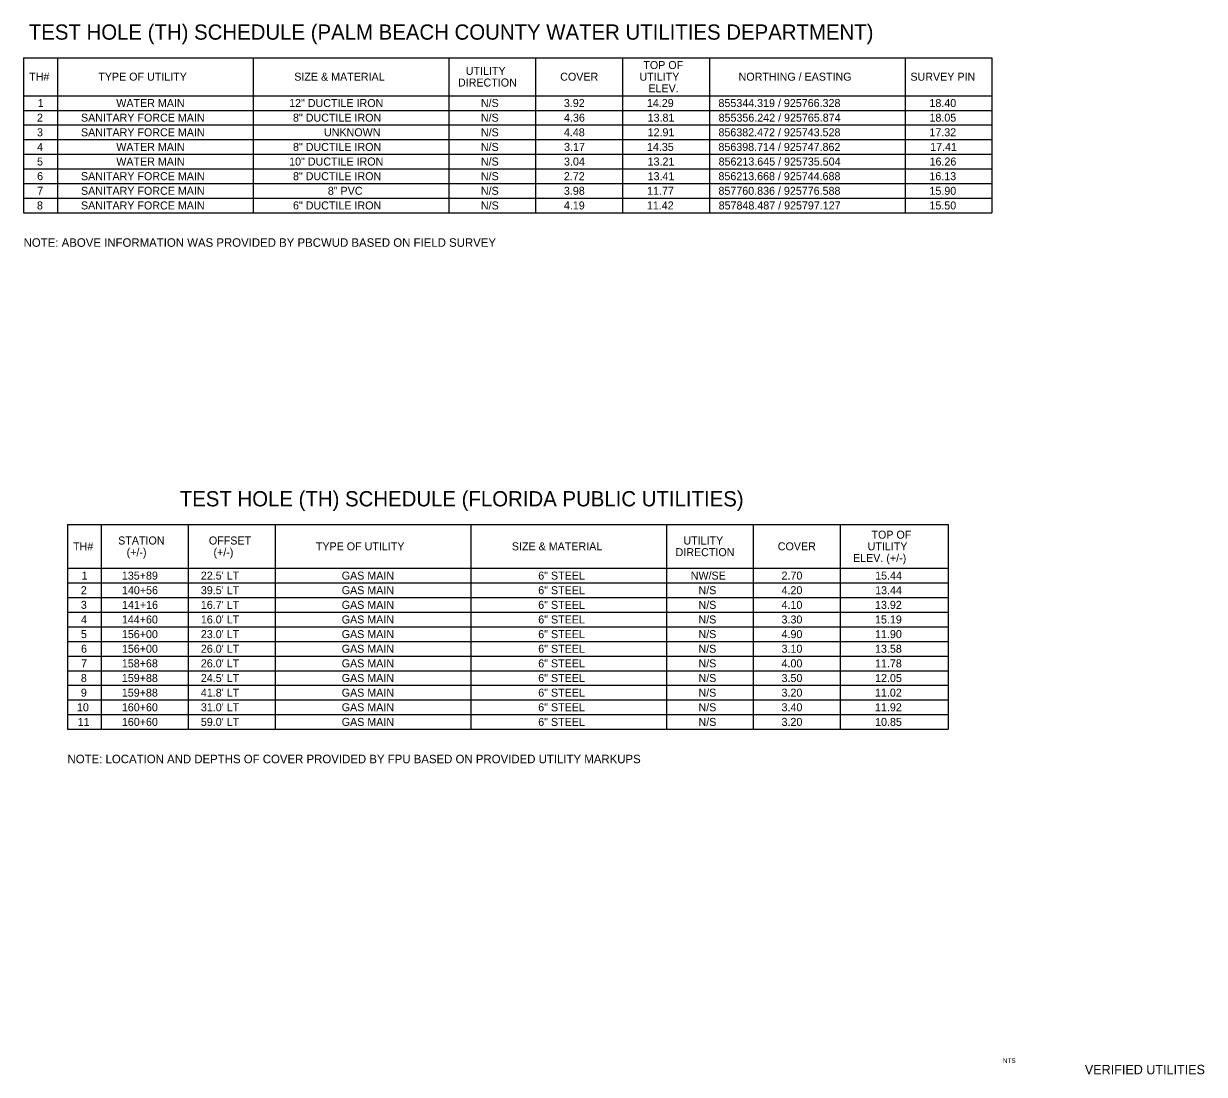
# Model space of a CAD drawing. Extents: x 3.74 to 13.42, y -0.23 to 8.39.
import ezdxf

# ---------------------------------------------------------------- set-up
doc = ezdxf.new("R2010")
doc.units = 0
for name, color, linetype in [('Default', 7, 'Continuous'), ('SumBoxBorder_dp', 7, 'Continuous'), ('SumBoxLines_dp', 7, 'Continuous'), ('TextLabel', 7, 'Continuous'), ('TextMinor', 7, 'Continuous')]:
    doc.layers.add(name, color=color, linetype=linetype)

msp = doc.modelspace()

# ---------------------------------------------------------------- linework, layer by layer
at = {"layer": 'SumBoxBorder_dp'}
for p, q in [((3.7378, 8.1135), (11.6803, 8.1135)), ((3.7378, 8.1135), (3.7378, 6.8415)), ((11.6803, 8.1135), (11.6803, 6.8415)), ((3.7378, 7.8015), (11.6803, 7.8015)), ((3.7378, 7.8015), (11.6803, 7.8015)), ((4.0978, 4.2857), (11.3203, 4.2857)), ((4.0978, 4.2857), (4.0978, 2.6057)), ((4.0978, 3.9257), (11.3203, 3.9257)), ((4.0978, 3.9257), (11.3203, 3.9257))]:
    msp.add_line(p, q, dxfattribs=at)
at = {"layer": 'SumBoxLines_dp'}
for p, q in [((4.0153, 8.1135), (4.0153, 6.8415)), ((4.0153, 8.1135), (4.0153, 6.8415)), ((5.6203, 8.1135), (5.6203, 6.8415)), ((5.6203, 8.1135), (5.6203, 6.8415)), ((7.2253, 8.1135), (7.2253, 6.8415)), ((7.2253, 8.1135), (7.2253, 6.8415)), ((7.9378, 8.1135), (7.9378, 6.8415)), ((7.9378, 8.1135), (7.9378, 6.8415)), ((8.6503, 8.1135), (8.6503, 6.8415)), ((8.6503, 8.1135), (8.6503, 6.8415)), ((9.3628, 8.1135), (9.3628, 6.8415)), ((9.3628, 8.1135), (9.3628, 6.8415)), ((10.9678, 8.1135), (10.9678, 6.8415)), ((10.9678, 8.1135), (10.9678, 6.8415)), ((3.7378, 7.6815), (11.6803, 7.6815)), ((3.7378, 7.6815), (11.6803, 7.6815)), ((3.7378, 7.5615), (11.6803, 7.5615)), ((3.7378, 7.5615), (11.6803, 7.5615)), ((3.7378, 7.4415), (11.6803, 7.4415)), ((3.7378, 7.4415), (11.6803, 7.4415)), ((3.7378, 7.3215), (11.6803, 7.3215)), ((3.7378, 7.3215), (11.6803, 7.3215)), ((3.7378, 7.2015), (11.6803, 7.2015)), ((3.7378, 7.2015), (11.6803, 7.2015)), ((3.7378, 7.0815), (11.6803, 7.0815)), ((3.7378, 7.0815), (11.6803, 7.0815)), ((3.7378, 6.9615), (11.6803, 6.9615)), ((3.7378, 6.9615), (11.6803, 6.9615)), ((3.7378, 6.8415), (11.6803, 6.8415)), ((4.3753, 4.2857), (4.3753, 2.6057)), ((4.3753, 4.2857), (4.3753, 2.6057)), ((5.0878, 4.2857), (5.0878, 2.6057)), ((5.0878, 4.2857), (5.0878, 2.6057)), ((5.8003, 4.2857), (5.8003, 2.6057)), ((5.8003, 4.2857), (5.8003, 2.6057)), ((7.4053, 4.2857), (7.4053, 2.6057)), ((7.4053, 4.2857), (7.4053, 2.6057)), ((9.0103, 4.2857), (9.0103, 2.6057)), ((9.0103, 4.2857), (9.0103, 2.6057)), ((9.7228, 4.2857), (9.7228, 2.6057)), ((9.7228, 4.2857), (9.7228, 2.6057)), ((10.4353, 4.2857), (10.4353, 2.6057)), ((10.4353, 4.2857), (10.4353, 2.6057)), ((11.3203, 4.2857), (11.3203, 2.6057)), ((4.0978, 3.8057), (11.3203, 3.8057)), ((4.0978, 3.8057), (11.3203, 3.8057)), ((4.0978, 3.6857), (11.3203, 3.6857)), ((4.0978, 3.6857), (11.3203, 3.6857)), ((4.0978, 3.5657), (11.3203, 3.5657)), ((4.0978, 3.5657), (11.3203, 3.5657)), ((4.0978, 3.4457), (11.3203, 3.4457)), ((4.0978, 3.4457), (11.3203, 3.4457)), ((4.0978, 3.3257), (11.3203, 3.3257)), ((4.0978, 3.3257), (11.3203, 3.3257)), ((4.0978, 3.2057), (11.3203, 3.2057)), ((4.0978, 3.2057), (11.3203, 3.2057)), ((4.0978, 3.0857), (11.3203, 3.0857)), ((4.0978, 3.0857), (11.3203, 3.0857)), ((4.0978, 2.9657), (11.3203, 2.9657)), ((4.0978, 2.9657), (11.3203, 2.9657)), ((4.0978, 2.8457), (11.3203, 2.8457)), ((4.0978, 2.8457), (11.3203, 2.8457)), ((4.0978, 2.7257), (11.3203, 2.7257)), ((4.0978, 2.7257), (11.3203, 2.7257)), ((4.0978, 2.6057), (11.3203, 2.6057))]:
    msp.add_line(p, q, dxfattribs=at)

# ---------------------------------------------------------------- texts
at = {"layer": 'Default'}
msp.add_text('   VERIFIED UTILITIES   ', height=0.077091, dxfattribs=at).set_placement((12.3568, -0.2241))
at = {"layer": 'TextLabel'}
for s, height, p in [('TEST HOLE (TH) SCHEDULE (PALM BEACH COUNTY WATER UTILITIES DEPARTMENT)', 0.125, (3.7804, 8.2611)), ('TOP OF', 0.06563, (8.8213, 8.0203)), ('TH#', 0.06563, (3.7835, 7.9247)), ('TYPE OF UTILITY', 0.065625, (4.3502, 7.9247)), ('SIZE & MATERIAL', 0.065625, (5.958, 7.9247)), ('DIRECTION', 0.06563, (7.3008, 7.8769)), ('UTILITY', 0.06563, (7.3645, 7.9725)), ('COVER', 0.06563, (8.1391, 7.9247)), ('UTILITY', 0.06563, (8.7895, 7.9247)), ('NORTHING / EASTING', 0.065625, (9.6027, 7.9247)), ('SURVEY PIN', 0.06563, (11.012, 7.9247)), ('ELEV.', 0.06563, (8.8625, 7.829)), ('1', 0.0656, (3.8537, 7.7087)), ('WATER MAIN', 0.06563, (4.498, 7.7087)), ('12" DUCTILE IRON', 0.065625, (5.9159, 7.7087)), ('N/S', 0.06563, (7.4886, 7.7087)), ('3.92', 0.06563, (8.1694, 7.7087)), ('14.29', 0.06563, (8.8505, 7.7087)), ('855344.319 / 925766.328', 0.065625, (9.4374, 7.7087)), ('18.40', 0.06563, (11.1681, 7.7087)), ('2', 0.0656, (3.8473, 7.5887)), ('SANITARY FORCE MAIN', 0.065625, (4.2083, 7.5887)), ('8" DUCTILE IRON', 0.065625, (5.9476, 7.5887)), ('N/S', 0.06563, (7.4886, 7.5887)), ('4.36', 0.06563, (8.1707, 7.5887)), ('13.81', 0.06563, (8.8564, 7.5887)), ('855356.242 / 925765.874', 0.065625, (9.4385, 7.5887)), ('18.05', 0.06563, (11.1684, 7.5887)), ('3', 0.0656, (3.8472, 7.4687)), ('SANITARY FORCE MAIN', 0.065625, (4.2083, 7.4687)), ('UNKNOWN', 0.06563, (6.2017, 7.4687)), ('N/S', 0.06563, (7.4886, 7.4687)), ('4.48', 0.06563, (8.1696, 7.4687)), ('12.91', 0.06563, (8.8564, 7.4687)), ('856382.472 / 925743.528', 0.065625, (9.4374, 7.4687)), ('17.32', 0.06563, (11.1676, 7.4687)), ('4', 0.0656, (3.8486, 7.3487)), ('WATER MAIN', 0.06563, (4.498, 7.3487)), ('8" DUCTILE IRON', 0.065625, (5.9476, 7.3487)), ('N/S', 0.06563, (7.4886, 7.3487)), ('3.17', 0.06563, (8.1712, 7.3487)), ('14.35', 0.06563, (8.8509, 7.3487)), ('856398.714 / 925747.862', 0.065625, (9.4372, 7.3487)), ('17.41', 0.06563, (11.1739, 7.3487)), ('5', 0.0656, (3.8481, 7.2287)), ('WATER MAIN', 0.06563, (4.498, 7.2287)), ('10" DUCTILE IRON', 0.065625, (5.9159, 7.2287)), ('N/S', 0.06563, (7.4886, 7.2287)), ('3.04', 0.06563, (8.1706, 7.2287)), ('13.21', 0.06563, (8.8564, 7.2287)), ('856213.645 / 925735.504', 0.065625, (9.4385, 7.2287)), ('16.26', 0.06563, (11.1689, 7.2287)), ('6', 0.0656, (3.8485, 7.1087)), ('SANITARY FORCE MAIN', 0.065625, (4.2083, 7.1087)), ('8" DUCTILE IRON', 0.065625, (5.9476, 7.1087)), ('N/S', 0.06563, (7.4886, 7.1087)), ('2.72', 0.06563, (8.1694, 7.1087)), ('13.41', 0.06563, (8.8564, 7.1087)), ('856213.668 / 925744.688', 0.065625, (9.4374, 7.1087)), ('16.13', 0.06563, (11.1676, 7.1087)), ('7', 0.0656, (3.8493, 6.9887)), ('SANITARY FORCE MAIN', 0.065625, (4.2083, 6.9887)), ('8" PVC', 0.06563, (6.2333, 6.9887)), ('N/S', 0.06563, (7.4886, 6.9887)), ('3.98', 0.06563, (8.1696, 6.9887)), ('11.77', 0.06563, (8.852, 6.9887)), ('857760.836 / 925776.588', 0.065625, (9.4374, 6.9887)), ('15.90', 0.06563, (11.1681, 6.9887)), ('8', 0.0656, (3.8475, 6.8687)), ('SANITARY FORCE MAIN', 0.065625, (4.2083, 6.8687)), ('6" DUCTILE IRON', 0.065625, (5.9476, 6.8687)), ('N/S', 0.06563, (7.4886, 6.8687)), ('4.19', 0.06563, (8.1697, 6.8687)), ('11.42', 0.06563, (8.8501, 6.8687)), ('857848.487 / 925797.127', 0.065625, (9.439, 6.8687)), ('15.50', 0.06563, (11.1681, 6.8687)), ('NOTE: ABOVE INFORMATION WAS PROVIDED BY PBCWUD BASED ON FIELD SURVEY', 0.07, (3.7378, 6.5623)), ('TEST HOLE (TH) SCHEDULE (FLORIDA PUBLIC UTILITIES)', 0.125, (5.0185, 4.4333)), ('STATION', 0.06563, (4.5134, 4.1207)), ('OFFSET', 0.06563, (5.2575, 4.1207)), ('UTILITY', 0.06563, (9.1495, 4.1207)), ('TOP OF', 0.06563, (10.6926, 4.1685)), ('TH#', 0.06563, (4.1435, 4.0729)), ('(+/-)', 0.06563, (4.5828, 4.0251)), ('(+/-)', 0.06563, (5.2953, 4.0251)), ('TYPE OF UTILITY', 0.065625, (6.1352, 4.0729)), ('SIZE & MATERIAL', 0.065625, (7.743, 4.0729)), ('DIRECTION', 0.06563, (9.0858, 4.0251)), ('COVER', 0.06563, (9.9241, 4.0729)), ('UTILITY', 0.06563, (10.6607, 4.0729)), ('ELEV. (+/-)', 0.065625, (10.5411, 3.9772)), ('1', 0.0656, (4.2137, 3.8329)), ('135+89', 0.06563, (4.5437, 3.8329)), ("22.5' LT", 0.06563, (5.1917, 3.8329)), ('GAS MAIN', 0.06563, (6.3473, 3.8329)), ('6" STEEL', 0.06563, (7.9591, 3.8329)), ('NW/SE', 0.06563, (9.2099, 3.8329)), ('2.70', 0.06563, (9.9549, 3.8329)), ('15.44', 0.06563, (10.7226, 3.8329)), ('2', 0.0656, (4.2073, 3.7129)), ('140+56', 0.06563, (4.5447, 3.7129)), ("39.5' LT", 0.06563, (5.1917, 3.7129)), ('GAS MAIN', 0.06563, (6.3473, 3.7129)), ('6" STEEL', 0.06563, (7.9591, 3.7129)), ('N/S', 0.06563, (9.2736, 3.7129)), ('4.20', 0.06563, (9.9549, 3.7129)), ('13.44', 0.06563, (10.7226, 3.7129)), ('3', 0.0656, (4.2072, 3.5929)), ('141+16', 0.06563, (4.5447, 3.5929)), ("16.7' LT", 0.06563, (5.1917, 3.5929)), ('GAS MAIN', 0.06563, (6.3473, 3.5929)), ('6" STEEL', 0.06563, (7.9591, 3.5929)), ('N/S', 0.06563, (9.2736, 3.5929)), ('4.10', 0.06563, (9.9549, 3.5929)), ('13.92', 0.06563, (10.7214, 3.5929)), ('4', 0.0656, (4.2086, 3.4729)), ('144+60', 0.06563, (4.5439, 3.4729)), ("16.0' LT", 0.06563, (5.1917, 3.4729)), ('GAS MAIN', 0.06563, (6.3473, 3.4729)), ('6" STEEL', 0.06563, (7.9591, 3.4729)), ('N/S', 0.06563, (9.2736, 3.4729)), ('3.30', 0.06563, (9.9549, 3.4729)), ('15.19', 0.06563, (10.7217, 3.4729)), ('5', 0.0656, (4.2081, 3.3529)), ('156+00', 0.06563, (4.5439, 3.3529)), ("23.0' LT", 0.06563, (5.1917, 3.3529)), ('GAS MAIN', 0.06563, (6.3473, 3.3529)), ('6" STEEL', 0.06563, (7.9591, 3.3529)), ('N/S', 0.06563, (9.2736, 3.3529)), ('4.90', 0.06563, (9.9549, 3.3529)), ('11.90', 0.06563, (10.7219, 3.3529)), ('6', 0.0656, (4.2085, 3.2329)), ('156+00', 0.06563, (4.5439, 3.2329)), ("26.0' LT", 0.06563, (5.1917, 3.2329)), ('GAS MAIN', 0.06563, (6.3473, 3.2329)), ('6" STEEL', 0.06563, (7.9591, 3.2329)), ('N/S', 0.06563, (9.2736, 3.2329)), ('3.10', 0.06563, (9.9549, 3.2329)), ('13.58', 0.06563, (10.7216, 3.2329)), ('7', 0.0656, (4.2093, 3.1129)), ('158+68', 0.06563, (4.5436, 3.1129)), ("26.0' LT", 0.06563, (5.1917, 3.1129)), ('GAS MAIN', 0.06563, (6.3473, 3.1129)), ('6" STEEL', 0.06563, (7.9591, 3.1129)), ('N/S', 0.06563, (9.2736, 3.1129)), ('4.00', 0.06563, (9.9549, 3.1129)), ('11.78', 0.06563, (10.7216, 3.1129)), ('8', 0.0656, (4.2075, 2.9929)), ('159+88', 0.06563, (4.5436, 2.9929)), ("24.5' LT", 0.06563, (5.1917, 2.9929)), ('GAS MAIN', 0.06563, (6.3473, 2.9929)), ('6" STEEL', 0.06563, (7.9591, 2.9929)), ('N/S', 0.06563, (9.2736, 2.9929)), ('3.50', 0.06563, (9.9549, 2.9929)), ('12.05', 0.06563, (10.7222, 2.9929)), ('9', 0.0656, (4.2076, 2.8729)), ('159+88', 0.06563, (4.5436, 2.8729)), ("41.8' LT", 0.06563, (5.1917, 2.8729)), ('GAS MAIN', 0.06563, (6.3473, 2.8729)), ('6" STEEL', 0.06563, (7.9591, 2.8729)), ('N/S', 0.06563, (9.2736, 2.8729)), ('3.20', 0.06563, (9.9549, 2.8729)), ('11.02', 0.06563, (10.7214, 2.8729)), ('10', 0.06563, (4.1756, 2.7529)), ('160+60', 0.06563, (4.5439, 2.7529)), ("31.0' LT", 0.06563, (5.1917, 2.7529)), ('GAS MAIN', 0.06563, (6.3473, 2.7529)), ('6" STEEL', 0.06563, (7.9591, 2.7529)), ('N/S', 0.06563, (9.2736, 2.7529)), ('3.40', 0.06563, (9.9549, 2.7529)), ('11.92', 0.06563, (10.7214, 2.7529)), ('11', 0.06563, (4.1815, 2.6329)), ('160+60', 0.06563, (4.5439, 2.6329)), ("59.0' LT", 0.06563, (5.1917, 2.6329)), ('GAS MAIN', 0.06563, (6.3473, 2.6329)), ('6" STEEL', 0.06563, (7.9591, 2.6329)), ('N/S', 0.06563, (9.2736, 2.6329)), ('3.20', 0.06563, (9.9549, 2.6329)), ('10.85', 0.06563, (10.7222, 2.6329)), ('NOTE: LOCATION AND DEPTHS OF COVER PROVIDED BY FPU BASED ON PROVIDED UTILITY MARKUPS', 0.07, (4.0978, 2.3265))]:
    msp.add_text(s, height=height, dxfattribs=at).set_placement(p)
at = {"layer": 'TextMinor'}
msp.add_text('NTS', height=0.03855, dxfattribs=at).set_placement((11.7691, -0.1311))

doc.saveas('drawing.dxf')
